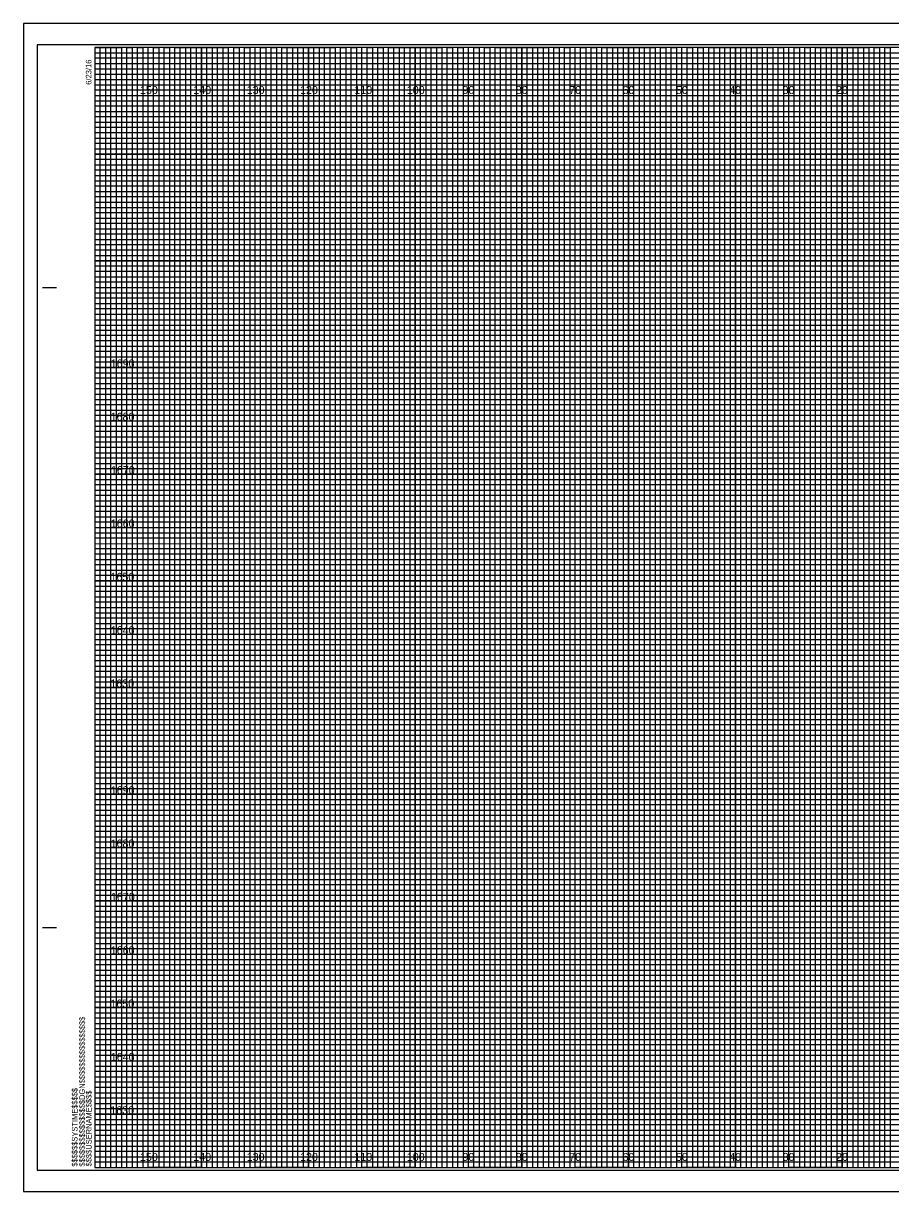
# Model space of a CAD drawing. Extents: x -419 to 4739, y -630 to 13534.
# Drawn here: x 1539.8 to 1702.3, y 855.2 to 1074.2 of the extents above; entities that cross this region are included whole.
import ezdxf

# ---------------------------------------------------------------- set-up
doc = ezdxf.new("R2010")
doc.units = 0
for name, color, linetype in [('Old_Level_62', 7, 'Continuous'), ('Pattern 1', 7, 'Continuous'), ('Pattern 18', 7, 'Continuous'), ('Pattern 4', 7, 'Continuous'), ('Pattern 5', 7, 'Continuous'), ('Prop Dimension', 7, 'Continuous'), ('Prop Horizontal Alignment', 7, 'Continuous'), ('Raster_Level_0', 7, 'Continuous'), ('Scratch_Level_0', 7, 'Continuous'), ('Scratch_Level_3', 7, 'Continuous'), ('Scratch_Level_5', 7, 'Continuous')]:
    doc.layers.add(name, color=color, linetype=linetype)

msp = doc.modelspace()

# ---------------------------------------------------------------- linework, layer by layer
at = {"layer": 'Old_Level_62'}
for p, q in [((1543.4, 1024.66), (1545.9, 1024.66)), ((1543.5, 1024.66), (1546, 1024.66)), ((1543.4, 904.66), (1545.9, 904.66)), ((1543.5, 904.66), (1546, 904.66)), ((1553.2, 859.66), (1553.2, 859.66)), ((1553.2, 859.66), (1553.2, 859.66)), ((1553.2, 859.66), (1553.2, 859.66)), ((1553.2, 859.66), (1553.2, 859.66)), ((1553.2, 859.66), (1553.2, 859.66)), ((1553.2, 859.66), (1553.2, 859.66)), ((1553.2, 859.66), (1553.2, 859.66))]:
    msp.add_line(p, q, dxfattribs=at)
msp.add_lwpolyline([(1873.2, 1069.66), (1553.2, 1069.66), (1553.2, 859.66), (1873.2, 859.66)], close=True, dxfattribs=at)
at = {"layer": 'Pattern 18'}
msp.add_lwpolyline([(1539.8, 855.16), (1876.5, 855.16), (1876.5, 1074.16), (1539.8, 1074.16)], close=True, dxfattribs=at)
at = {"layer": 'Pattern 4'}
for p, q in [((1553.2, 1068.66), (1813.2, 1068.66)), ((1813.2, 1067.64), (1553.2, 1067.64)), ((1553.2, 1067.64), (1553.2, 1066.66)), ((1553.2, 1066.66), (1813.2, 1066.66)), ((1813.2, 1065.55), (1553.2, 1065.55)), ((1553.2, 1065.55), (1553.2, 1063.66)), ((1553.2, 1063.66), (1873.2, 1063.66))]:
    msp.add_line(p, q, dxfattribs=at)
for points in [[(1553.2, 1062.66), (1823.2, 1062.66), (1873.2, 1062.66), (1873.2, 1061.66), (1553.2, 1061.66)], [(1553.2, 1060.66), (1873.2, 1060.66), (1873.2, 1058.66), (1553.2, 1058.66)], [(1553.2, 1057.66), (1873.2, 1057.66), (1873.2, 1056.66), (1553.2, 1056.64)], [(1553.2, 1055.66), (1873.2, 1055.66), (1873.2, 1053.66), (1553.2, 1053.66)], [(1553.2, 1052.66), (1873.2, 1052.66), (1873.2, 1051.66), (1553.2, 1051.66)], [(1553.2, 1050.66), (1873.2, 1050.66), (1873.2, 1048.66), (1553.2, 1048.66)], [(1553.2, 1047.66), (1873.2, 1047.66), (1873.2, 1046.66), (1553.2, 1046.66)], [(1553.2, 1045.66), (1873.2, 1045.66), (1873.2, 1043.66), (1553.2, 1043.66)], [(1553.2, 1042.66), (1873.2, 1042.66), (1873.2, 1041.66), (1553.2, 1041.66)], [(1553.2, 1040.66), (1873.2, 1040.66), (1873.2, 1038.66), (1553.2, 1038.66)], [(1553.2, 1037.66), (1873.2, 1037.66), (1873.2, 1036.66), (1553.2, 1036.66)], [(1553.2, 1035.66), (1873.2, 1035.66), (1873.2, 1033.61), (1873.2, 1032.66), (1873.2, 1031.66), (1553.2, 1031.66)], [(1553.2, 1033.66), (1873.2, 1033.66), (1873.2, 1032.66), (1553.2, 1032.66)], [(1553.2, 1030.66), (1873.2, 1030.66), (1873.2, 1028.66), (1553.2, 1028.69)], [(1553.2, 1028.69), (1873.2, 1028.66), (1873.2, 1027.66), (1553.2, 1027.66)], [(1553.2, 1026.66), (1873.2, 1026.66), (1873.2, 1025.66), (1553.2, 1025.66)], [(1553.2, 1023.66), (1873.2, 1023.66), (1873.2, 1022.66), (1553.2, 1022.66)], [(1553.2, 1021.66), (1873.2, 1021.66), (1873.2, 1020.66), (1553.2, 1020.66)], [(1553.13, 1018.55), (1873.2, 1018.55), (1873.2, 1017.54), (1553.13, 1017.54)], [(1553.2, 1016.66), (1873.2, 1016.66), (1873.2, 1015.66), (1553.2, 1015.66)], [(1553.2, 1013.66), (1873.2, 1013.66), (1873.2, 1012.66), (1553.2, 1012.66)], [(1553.2, 1011.66), (1873.2, 1011.66), (1873.2, 1010.66), (1553.2, 1010.66)], [(1553.2, 1008.66), (1873.2, 1008.66), (1873.2, 1007.66), (1553.2, 1007.66)], [(1553.2, 1006.66), (1873.2, 1006.66), (1873.2, 1005.66), (1553.2, 1005.66)], [(1553.2, 1003.66), (1873.2, 1003.66), (1873.2, 1002.66), (1553.2, 1002.66)], [(1553.2, 1001.66), (1873.2, 1001.66), (1873.2, 1000.66), (1553.2, 1000.66)], [(1553.2, 998.66), (1873.2, 998.66), (1873.19, 997.64), (1553.2, 997.66)], [(1553.2, 996.66), (1873.2, 996.66), (1873.2, 995.66), (1553.2, 995.66)], [(1553.2, 993.66), (1873.2, 993.66), (1873.2, 992.66), (1553.2, 992.66)], [(1553.2, 991.66), (1873.2, 991.66), (1873.2, 990.66), (1553.2, 990.66)], [(1553.2, 988.66), (1873.2, 988.66), (1873.2, 987.66), (1553.2, 987.66)], [(1553.2, 986.66), (1873.2, 986.66), (1873.2, 985.66), (1553.2, 985.66)], [(1553.2, 983.66), (1873.2, 983.66), (1873.2, 982.66), (1553.2, 982.66)], [(1553.2, 981.66), (1873.2, 981.66), (1873.2, 980.66), (1553.2, 980.66)], [(1553.2, 978.66), (1873.2, 978.66), (1873.2, 977.66), (1553.2, 977.66)], [(1553.2, 976.65), (1873.27, 976.57), (1873.2, 975.66), (1553.2, 975.66)], [(1553.2, 973.66), (1873.2, 973.66), (1873.2, 972.66), (1553.2, 972.66)], [(1553.2, 971.66), (1873.2, 971.66), (1873.2, 970.66), (1553.2, 970.66)], [(1553.2, 968.66), (1873.2, 968.66), (1873.2, 967.66), (1553.2, 967.66)], [(1553.2, 966.66), (1873.2, 966.66), (1873.2, 965.66), (1553.2, 965.66)], [(1553.2, 963.66), (1873.2, 963.66), (1873.2, 962.66), (1553.2, 962.66)], [(1553.2, 961.66), (1873.2, 961.66), (1873.2, 960.66), (1553.2, 960.66)], [(1553.2, 958.66), (1873.2, 958.66), (1873.2, 957.66), (1553.2, 957.66)], [(1553.2, 956.66), (1873.2, 956.66), (1873.2, 955.66), (1553.2, 955.66)], [(1553.2, 953.66), (1873.2, 953.66), (1873.2, 952.66), (1553.2, 952.66)], [(1553.2, 951.66), (1873.2, 951.66), (1873.2, 950.66), (1553.2, 950.66)], [(1553.2, 948.66), (1873.2, 948.66), (1873.2, 947.66), (1553.2, 947.66)], [(1553.2, 946.66), (1873.2, 946.66), (1873.2, 945.66), (1553.2, 945.66)], [(1553.2, 943.66), (1873.2, 943.66), (1873.2, 942.66), (1553.2, 942.66)], [(1553.2, 941.66), (1873.2, 941.66), (1873.2, 940.66), (1553.2, 940.66)], [(1553.2, 938.66), (1873.2, 938.66), (1873.19, 937.64), (1553.2, 937.66)], [(1553.2, 936.66), (1873.2, 936.66), (1873.2, 935.66), (1553.2, 935.66)], [(1553.2, 933.66), (1873.2, 933.66), (1873.2, 932.66), (1553.2, 932.66)], [(1553.2, 931.66), (1873.2, 931.66), (1873.2, 930.66), (1553.2, 930.66)], [(1553.2, 928.66), (1873.2, 928.66), (1873.2, 927.66), (1553.2, 927.66)], [(1553.2, 926.66), (1873.2, 926.66), (1873.2, 925.66), (1553.2, 925.66)], [(1553.2, 923.66), (1873.2, 923.66), (1873.2, 922.66), (1553.2, 922.66)], [(1553.2, 921.66), (1873.2, 921.66), (1873.2, 920.66), (1553.2, 920.66)], [(1553.2, 918.66), (1873.2, 918.66), (1873.2, 917.66), (1553.2, 917.66)], [(1553.2, 916.65), (1873.27, 916.57), (1873.2, 915.66), (1553.2, 915.66)], [(1553.2, 913.66), (1873.2, 913.66), (1873.2, 912.66), (1553.2, 912.66)], [(1553.2, 911.66), (1873.2, 911.66), (1873.2, 910.66), (1553.2, 910.66)], [(1553.2, 908.66), (1873.2, 908.66), (1873.2, 907.66), (1553.2, 907.66)], [(1553.2, 906.66), (1873.2, 906.66), (1873.2, 905.66), (1553.2, 905.66)], [(1553.2, 903.66), (1873.2, 903.66), (1873.2, 902.66), (1553.2, 902.66)], [(1553.2, 901.66), (1873.2, 901.66), (1873.2, 900.66), (1553.2, 900.66)], [(1553.2, 898.66), (1873.2, 898.66), (1873.2, 897.66), (1553.2, 897.66)], [(1553.2, 896.66), (1873.2, 896.66), (1873.2, 895.66), (1553.2, 895.66)], [(1553.2, 893.66), (1873.2, 893.66), (1873.2, 892.66), (1553.2, 892.66)], [(1553.2, 891.66), (1873.2, 891.66), (1873.2, 890.66), (1553.2, 890.66)], [(1553.2, 888.66), (1873.2, 888.66), (1873.2, 887.66), (1553.2, 887.66)], [(1553.2, 886.66), (1873.2, 886.66), (1873.2, 885.66), (1553.2, 885.66)], [(1553.2, 883.66), (1873.2, 883.66), (1873.2, 882.66), (1553.2, 882.66)], [(1553.2, 881.66), (1873.2, 881.66), (1873.2, 880.66), (1553.2, 880.66)], [(1553.2, 878.66), (1873.2, 878.66), (1873.2, 877.66), (1553.2, 877.66)], [(1553.2, 876.66), (1873.2, 876.66), (1873.2, 875.66), (1553.2, 875.66)], [(1553.2, 873.66), (1873.2, 873.66), (1873.2, 872.66), (1553.2, 872.66)], [(1553.2, 871.66), (1873.2, 871.66), (1873.2, 870.66), (1553.2, 870.66)], [(1553.2, 868.66), (1873.2, 868.66), (1873.2, 867.66), (1553.2, 867.66)], [(1553.2, 866.66), (1873.2, 866.66), (1873.2, 865.66), (1553.2, 865.66)], [(1553.2, 863.66), (1873.2, 863.66), (1873.2, 862.66), (1553.2, 862.66)], [(1553.2, 861.66), (1873.2, 861.66), (1873.2, 860.66), (1553.2, 860.66)]]:
    msp.add_lwpolyline(points, dxfattribs=at)
at = {"layer": 'Pattern 5'}
for p, q in [((1876.5, 1074.16), (1539.8, 1074.16)), ((1539.8, 1074.16), (1539.8, 855.16)), ((1539.8, 855.16), (1876.5, 855.16))]:
    msp.add_line(p, q, dxfattribs=at)
at = {"layer": 'Prop Dimension'}
for points in [[(1553.2, 859.66), (1554.2, 859.66), (1554.2, 1069.66), (1555.2, 1069.66), (1555.2, 859.66)], [(1555.2, 859.66), (1556.2, 859.66), (1556.2, 1069.66), (1557.2, 1069.66), (1557.2, 859.66)], [(1558.2, 859.66), (1559.2, 859.66), (1559.2, 1069.66), (1560.2, 1069.66), (1560.2, 859.66)], [(1560.2, 859.66), (1561.2, 859.66), (1561.2, 1069.66), (1562.2, 1069.66), (1562.2, 859.66)], [(1563.2, 859.66), (1564.2, 859.66), (1564.2, 1069.66), (1565.2, 1069.66), (1565.2, 859.66)], [(1565.2, 859.66), (1566.2, 859.66), (1566.2, 1069.66), (1567.2, 1069.66), (1567.2, 859.66)], [(1568.2, 859.66), (1569.2, 859.66), (1569.2, 1069.66), (1570.2, 1069.66), (1570.2, 859.66)], [(1570.2, 859.66), (1571.2, 859.66), (1571.2, 1069.66), (1572.2, 1069.66), (1572.2, 859.66)], [(1573.2, 859.66), (1574.2, 859.66), (1574.2, 1069.66), (1575.2, 1069.66), (1575.2, 859.66)], [(1575.2, 859.66), (1576.2, 859.66), (1576.2, 1069.66), (1577.2, 1069.66), (1577.2, 859.66)], [(1578.2, 859.66), (1579.2, 859.66), (1579.2, 1069.66), (1580.2, 1069.66), (1580.2, 859.66)], [(1580.2, 859.66), (1581.2, 859.66), (1581.2, 1069.66), (1582.2, 1069.66), (1582.2, 859.66)], [(1583.2, 859.66), (1584.2, 859.66), (1584.2, 1069.66), (1585.2, 1069.66), (1585.2, 859.66)], [(1585.2, 859.66), (1586.2, 859.66), (1586.2, 1069.66), (1587.2, 1069.66), (1587.2, 859.66)], [(1588.2, 859.66), (1589.2, 859.66), (1589.2, 1069.66), (1590.2, 1069.66), (1590.2, 859.66)], [(1590.2, 859.66), (1591.2, 859.66), (1591.2, 1069.66), (1592.2, 1069.66), (1592.2, 859.66)], [(1593.2, 859.66), (1594.2, 859.66), (1594.2, 1069.66), (1595.2, 1069.66), (1595.2, 859.66)], [(1595.2, 859.66), (1596.2, 859.66), (1596.2, 1069.66), (1597.2, 1069.66), (1597.2, 859.66)], [(1598.2, 859.66), (1599.2, 859.66), (1599.2, 1069.66), (1600.2, 1069.66), (1600.2, 859.66)], [(1600.2, 859.66), (1601.2, 859.66), (1601.2, 1069.66), (1602.2, 1069.66), (1602.2, 859.66)], [(1603.2, 859.66), (1604.2, 859.66), (1604.2, 1069.66), (1605.2, 1069.66), (1605.2, 859.66)], [(1605.2, 859.66), (1606.2, 859.66), (1606.2, 1069.66), (1607.2, 1069.66), (1607.2, 859.66)], [(1608.2, 859.66), (1609.2, 859.66), (1609.2, 1069.66), (1610.2, 1069.66), (1610.2, 859.66)], [(1610.2, 859.66), (1611.2, 859.66), (1611.2, 1069.66), (1612.2, 1069.66), (1612.2, 859.66)], [(1613.2, 859.66), (1614.2, 859.66), (1614.2, 1069.66), (1615.2, 1069.66), (1615.2, 859.66)], [(1615.2, 859.66), (1616.2, 859.66), (1616.2, 1069.66), (1617.2, 1069.66), (1617.2, 859.66)], [(1618.2, 859.66), (1619.2, 859.66), (1619.2, 1069.66), (1620.2, 1069.66), (1620.2, 859.66)], [(1620.2, 859.66), (1621.2, 859.66), (1621.2, 1069.66), (1622.2, 1069.66), (1622.2, 859.66)], [(1623.2, 859.66), (1624.2, 859.66), (1624.2, 1069.66), (1625.2, 1069.66), (1625.2, 859.66)], [(1625.2, 859.66), (1626.2, 859.66), (1626.2, 1069.66), (1627.2, 1069.66), (1627.2, 859.66)], [(1628.2, 859.66), (1629.2, 859.66), (1629.2, 1069.66), (1630.2, 1069.66), (1630.2, 859.66)], [(1630.2, 859.66), (1631.2, 859.66), (1631.2, 1069.66), (1632.2, 1069.66), (1632.2, 859.66)], [(1633.2, 859.66), (1634.2, 859.66), (1634.2, 1069.66), (1635.2, 1069.66), (1635.2, 859.66)], [(1635.2, 859.66), (1636.2, 859.66), (1636.2, 1069.66), (1637.2, 1069.66), (1637.2, 859.66)], [(1638.2, 859.66), (1639.2, 859.66), (1639.2, 1069.66), (1640.2, 1069.66), (1640.2, 859.66)], [(1640.2, 859.66), (1641.2, 859.66), (1641.2, 1069.66), (1642.2, 1069.66), (1642.2, 859.66)], [(1643.2, 859.66), (1644.2, 859.66), (1644.2, 1069.66), (1645.2, 1069.66), (1645.2, 859.66)], [(1645.2, 859.66), (1646.2, 859.66), (1646.2, 1069.66), (1647.2, 1069.66), (1647.2, 859.66)], [(1648.2, 859.66), (1649.2, 859.66), (1649.2, 1069.66), (1650.2, 1069.66), (1650.2, 859.66)], [(1650.2, 859.66), (1651.2, 859.66), (1651.2, 1069.66), (1652.2, 1069.66), (1652.2, 859.66)], [(1653.2, 859.66), (1654.2, 859.66), (1654.2, 1069.66), (1655.2, 1069.66), (1655.2, 859.66)], [(1655.2, 859.66), (1656.2, 859.66), (1656.2, 1069.66), (1657.2, 1069.66), (1657.2, 859.66)], [(1658.2, 859.66), (1659.2, 859.66), (1659.2, 1069.66), (1660.2, 1069.66), (1660.2, 859.66)], [(1660.2, 859.66), (1661.2, 859.66), (1661.2, 1069.66), (1662.2, 1069.66), (1662.2, 859.66)], [(1663.2, 859.66), (1664.2, 859.66), (1664.2, 1069.66), (1665.2, 1069.66), (1665.2, 859.66)], [(1665.2, 859.66), (1666.2, 859.66), (1666.2, 1069.66), (1667.2, 1069.66), (1667.2, 859.66)], [(1668.2, 859.66), (1669.2, 859.66), (1669.2, 1069.66), (1670.2, 1069.66), (1670.2, 859.66)], [(1670.2, 859.66), (1671.2, 859.66), (1671.2, 1069.66), (1672.2, 1069.66), (1672.2, 859.66)], [(1673.2, 859.66), (1674.2, 859.66), (1674.2, 1069.66), (1675.2, 1069.66), (1675.2, 859.66)], [(1675.2, 859.66), (1676.2, 859.66), (1676.2, 1069.66), (1677.2, 1069.66), (1677.2, 859.66)], [(1678.2, 859.66), (1679.2, 859.66), (1679.2, 1069.66), (1680.2, 1069.66), (1680.2, 859.66)], [(1680.2, 859.66), (1681.2, 859.66), (1681.2, 1069.66), (1682.2, 1069.66), (1682.2, 859.66)], [(1683.2, 859.66), (1684.2, 859.66), (1684.2, 1069.66), (1685.2, 1069.66), (1685.2, 859.66)], [(1685.2, 859.66), (1686.2, 859.66), (1686.2, 1069.66), (1687.2, 1069.66), (1687.2, 859.66)], [(1688.2, 859.66), (1689.2, 859.66), (1689.2, 1069.66), (1690.2, 1069.66), (1690.2, 859.66)], [(1690.2, 859.66), (1691.2, 859.66), (1691.2, 1069.66), (1692.2, 1069.66), (1692.2, 859.66)], [(1693.2, 859.66), (1694.2, 859.66), (1694.2, 1069.66), (1695.2, 1069.66), (1695.2, 859.66)], [(1695.2, 859.66), (1696.2, 859.66), (1696.2, 1069.66), (1697.2, 1069.66), (1697.2, 859.66)], [(1698.2, 859.66), (1699.2, 859.66), (1699.2, 1069.66), (1700.2, 1069.66), (1700.2, 859.66)], [(1700.2, 859.66), (1701.2, 859.66), (1701.2, 1069.66), (1702.2, 1069.66), (1702.2, 859.66)]]:
    msp.add_lwpolyline(points, dxfattribs=at)
at = {"layer": 'Prop Horizontal Alignment'}
for points in [[(1553.2, 1069.66), (1558.2, 1069.66), (1558.2, 859.66), (1568.2, 859.66), (1568.2, 1069.66), (1578.2, 1069.66), (1578.2, 859.66), (1588.2, 859.66), (1588.2, 1069.66), (1598.2, 1069.66), (1598.2, 859.66), (1608.2, 859.66), (1608.2, 1069.66), (1618.2, 1069.66), (1618.2, 859.66), (1628.2, 859.66), (1628.2, 1069.66), (1638.2, 1069.66), (1638.2, 859.66), (1648.2, 859.66), (1648.2, 1069.66), (1658.2, 1069.66), (1658.2, 859.66), (1668.2, 859.66), (1668.2, 1069.66), (1678.2, 1069.66), (1678.2, 859.66), (1688.2, 859.66), (1688.2, 1069.66), (1698.2, 1069.66), (1698.2, 859.66), (1708.2, 859.66)], [(1553.2, 1064.66), (1828.2, 1064.66)], [(1553.2, 1044.66), (1873.2, 1044.66), (1873.2, 1054.66), (1553.2, 1054.66)], [(1553.2, 1024.66), (1873.2, 1024.66), (1873.2, 1034.66), (1553.2, 1034.66)], [(1553.2, 1004.66), (1873.2, 1004.66), (1873.2, 1014.66), (1553.2, 1014.66)], [(1553.2, 984.66), (1873.2, 984.66), (1873.2, 994.66), (1553.2, 994.66)], [(1553.2, 964.66), (1873.2, 964.66), (1873.2, 974.66), (1553.2, 974.66)], [(1553.2, 944.66), (1873.2, 944.66), (1873.2, 954.66), (1553.2, 954.66)], [(1553.2, 924.66), (1873.2, 924.66), (1873.2, 934.66), (1553.2, 934.66)], [(1553.2, 904.66), (1873.2, 904.66), (1873.2, 914.66), (1553.2, 914.66)], [(1553.2, 884.66), (1873.2, 884.66), (1873.2, 894.66), (1553.2, 894.66)], [(1553.2, 864.66), (1873.2, 864.66), (1873.2, 874.66), (1553.2, 874.66)]]:
    msp.add_lwpolyline(points, dxfattribs=at)
at = {"layer": 'Scratch_Level_0'}
for p, q in [((1563.2, 859.66), (1563.2, 1069.66)), ((1573.2, 859.66), (1573.2, 1069.66)), ((1583.2, 859.66), (1583.2, 1069.66)), ((1593.2, 859.66), (1593.2, 1069.66)), ((1603.2, 859.66), (1603.2, 1069.66)), ((1613.2, 859.66), (1613.2, 1069.66)), ((1623.2, 859.66), (1623.2, 1069.66)), ((1633.2, 859.66), (1633.2, 1069.66)), ((1643.2, 859.66), (1643.2, 1069.66)), ((1653.2, 859.66), (1653.2, 1069.66)), ((1663.2, 859.66), (1663.2, 1069.66)), ((1673.2, 859.66), (1673.2, 1069.66)), ((1683.2, 859.66), (1683.2, 1069.66)), ((1693.2, 859.66), (1693.2, 1069.66)), ((1553.2, 1059.66), (1873.2, 1059.66)), ((1553.2, 1049.66), (1873.2, 1049.66)), ((1553.2, 1039.66), (1873.2, 1039.66)), ((1553.2, 1029.66), (1873.2, 1029.66)), ((1553.2, 1019.66), (1873.2, 1019.66)), ((1553.2, 1009.66), (1873.2, 1009.66)), ((1553.2, 999.66), (1873.2, 999.66)), ((1553.2, 989.66), (1873.2, 989.66)), ((1553.2, 979.66), (1873.2, 979.66)), ((1553.2, 969.66), (1873.2, 969.66)), ((1553.2, 959.66), (1873.2, 959.66)), ((1553.2, 949.66), (1873.2, 949.66)), ((1553.2, 939.66), (1873.2, 939.66)), ((1553.2, 929.66), (1873.2, 929.66)), ((1553.2, 919.66), (1873.2, 919.66)), ((1553.2, 909.66), (1873.2, 909.66)), ((1553.2, 899.66), (1873.2, 899.66)), ((1553.2, 889.66), (1873.2, 889.66)), ((1553.2, 879.66), (1873.2, 879.66)), ((1553.2, 869.66), (1873.2, 869.66))]:
    msp.add_line(p, q, dxfattribs=at)
at = {"layer": 'Scratch_Level_3'}
for p, q in [((1563.2, 1069.66), (1553.2, 1069.66)), ((1563.2, 859.66), (1563.2, 1069.66)), ((1583.2, 1069.66), (1573.2, 1069.66)), ((1573.2, 1069.66), (1573.2, 859.66)), ((1583.2, 859.66), (1583.2, 1069.66)), ((1603.2, 1069.66), (1593.2, 1069.66)), ((1593.2, 1069.66), (1593.2, 859.66)), ((1603.2, 859.66), (1603.2, 1069.66)), ((1623.2, 1069.66), (1613.2, 1069.66)), ((1613.2, 1069.66), (1613.2, 859.66)), ((1623.2, 859.66), (1623.2, 1069.66)), ((1643.2, 1069.66), (1633.2, 1069.66)), ((1633.2, 1069.66), (1633.2, 859.66)), ((1643.2, 859.66), (1643.2, 1069.66)), ((1663.2, 1069.66), (1653.2, 1069.66)), ((1653.2, 1069.66), (1653.2, 859.66)), ((1663.2, 859.66), (1663.2, 1069.66)), ((1683.2, 1069.66), (1673.2, 1069.66)), ((1673.2, 1069.66), (1673.2, 859.66)), ((1683.2, 859.66), (1683.2, 1069.66)), ((1703.2, 1069.66), (1693.2, 1069.66)), ((1693.2, 1069.66), (1693.2, 859.66)), ((1573.2, 859.66), (1563.2, 859.66)), ((1593.2, 859.66), (1583.2, 859.66)), ((1613.2, 859.66), (1603.2, 859.66)), ((1633.2, 859.66), (1623.2, 859.66)), ((1653.2, 859.66), (1643.2, 859.66)), ((1673.2, 859.66), (1663.2, 859.66)), ((1693.2, 859.66), (1683.2, 859.66))]:
    msp.add_line(p, q, dxfattribs=at)
for points in [[(1553.2, 1059.66), (1873.2, 1059.66), (1873.2, 1049.66), (1553.2, 1049.66)], [(1553.2, 1039.66), (1873.2, 1039.66), (1873.2, 1029.66), (1553.2, 1029.66)], [(1553.2, 1019.66), (1873.2, 1019.66), (1873.2, 1009.66), (1553.2, 1009.66)], [(1553.2, 999.66), (1873.2, 999.66), (1873.2, 989.66), (1553.2, 989.66)], [(1553.2, 979.66), (1873.2, 979.66), (1873.2, 969.66), (1553.2, 969.66)], [(1553.2, 959.66), (1873.2, 959.66), (1873.2, 949.66), (1553.2, 949.66)], [(1553.2, 939.66), (1873.2, 939.66), (1873.2, 929.66), (1553.2, 929.66)], [(1553.2, 919.66), (1873.2, 919.66), (1873.2, 909.66), (1553.2, 909.66)], [(1553.2, 899.66), (1873.2, 899.66), (1873.2, 889.66), (1553.2, 889.66)], [(1553.2, 879.66), (1873.2, 879.66), (1873.2, 869.66), (1553.2, 869.66)]]:
    msp.add_lwpolyline(points, dxfattribs=at)
at = {"layer": 'Scratch_Level_5'}
msp.add_lwpolyline([(1542.4, 859.16), (1875.6, 859.16), (1875.6, 1070.16), (1542.4, 1070.16)], close=True, dxfattribs=at)

# ---------------------------------------------------------------- texts
at = {"layer": 'Old_Level_62'}
for s, p in [('6/23/16', (1552.55, 1062.66)), ('$$$$$$$$$$$$$$$$DGN$$$$$$$$$$$$$$$$', (1551.32, 859.84)), ('$$$$$$SYSTIME$$$$$', (1549.94, 859.84)), ('$$$$USERNAME$$$$', (1552.58, 859.89))]:
    msp.add_text(s, height=1.05, rotation=90, dxfattribs=at).set_placement(p)
at = {"layer": 'Pattern 1'}
for s, p in [('1690', (1556.17, 1009.66)), ('1680', (1556.14, 999.66)), ('1670', (1556.2, 989.66)), ('1660', (1556.17, 979.66)), ('1650', (1556.12, 969.66)), ('1640', (1556.17, 959.66)), ('1630', (1556.08, 949.66)), ('1690', (1556.17, 929.66)), ('1680', (1556.14, 919.66)), ('1670', (1556.2, 909.66)), ('1660', (1556.17, 899.66)), ('1650', (1556.12, 889.66)), ('1640', (1556.17, 879.66)), ('1630', (1556.08, 869.66))]:
    msp.add_text(s, height=1.5, dxfattribs=at).set_placement(p)
at = {"layer": 'Raster_Level_0'}
for s, p in [('150', (1561.64, 1060.91)), ('140', (1571.64, 1060.91)), ('130', (1581.64, 1060.91)), ('120', (1591.64, 1060.91)), ('110', (1601.82, 1060.91)), ('100', (1611.64, 1060.91)), ('90', (1622.06, 1060.91)), ('80', (1632.06, 1060.91)), ('70', (1642.06, 1060.91)), ('60', (1652.06, 1060.91)), ('50', (1662.06, 1060.91)), ('40', (1672.06, 1060.91)), ('30', (1682.06, 1060.91)), ('20', (1692.06, 1060.91)), ('150', (1561.64, 860.91)), ('140', (1571.64, 860.91)), ('130', (1581.64, 860.91)), ('120', (1591.64, 860.91)), ('110', (1601.82, 860.91)), ('100', (1611.64, 860.91)), ('90', (1622.06, 860.91)), ('80', (1632.06, 860.91)), ('70', (1642.06, 860.91)), ('60', (1652.06, 860.91)), ('50', (1662.06, 860.91)), ('40', (1672.06, 860.91)), ('30', (1682.06, 860.91)), ('20', (1692.06, 860.91))]:
    msp.add_text(s, height=1.5, dxfattribs=at).set_placement(p)

doc.saveas('drawing.dxf')
